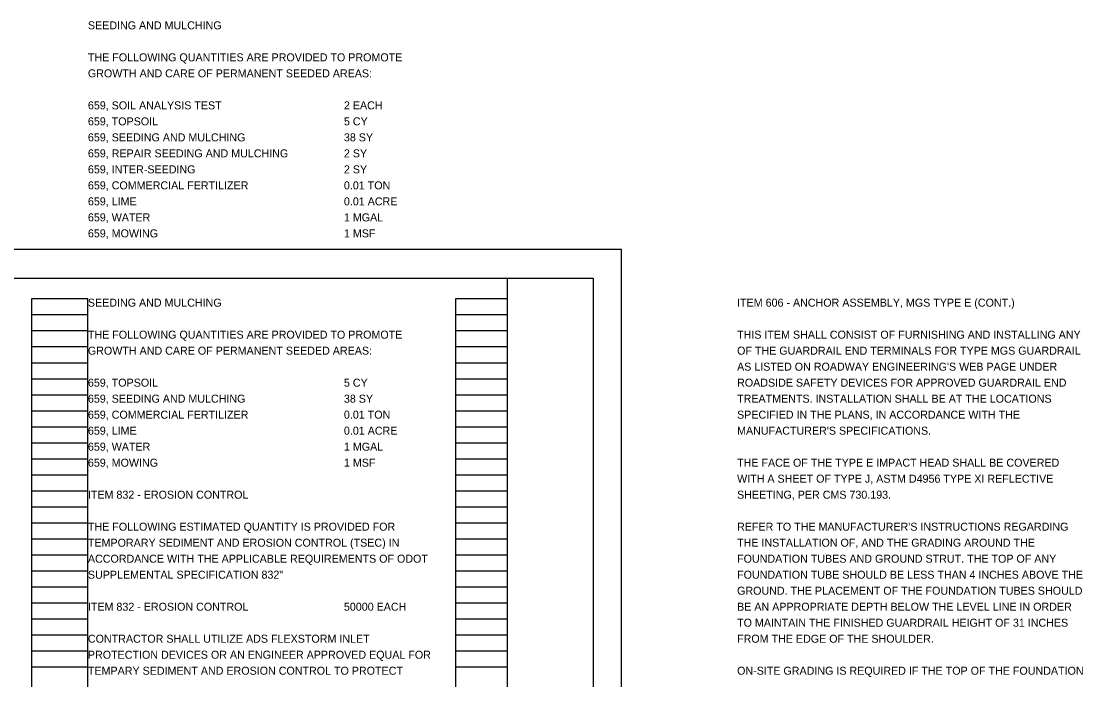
# Model space of a CAD drawing. Extents: x 0 to 42.1, y 0 to 26.
# Drawn here: x 23.49 to 42.07, y 14.47 to 25.99 of the extents above; entities that cross this region are included whole.
import ezdxf

# ---------------------------------------------------------------- set-up
doc = ezdxf.new("R2010")
doc.units = 0
for name, color, linetype in [('SH_Border', 7, 'Continuous'), ('SH_Cut_Line', 7, 'Continuous'), ('SH_Data', 7, 'Continuous'), ('SH_Text', 7, 'Continuous')]:
    doc.layers.add(name, color=color, linetype=linetype)

msp = doc.modelspace()

# ---------------------------------------------------------------- linework, layer by layer
at = {"layer": 'SH_Border'}
msp.add_line((32, 0.5), (32, 21.5), dxfattribs=at)
msp.add_lwpolyline([(1.5, 21.5), (33.5, 21.5), (33.5, 0.5), (1.5, 0.5)], close=True, dxfattribs=at)
at = {"layer": 'SH_Cut_Line'}
msp.add_lwpolyline([(0, 0), (34, 0), (34, 22), (0, 22)], close=True, dxfattribs=at)
at = {"layer": 'SH_Data'}
for p, q in [((23.68, 0.98), (23.68, 21.14)), ((23.68, 21.14), (24.66, 21.14)), ((24.66, 0.98), (24.66, 21.14)), ((31.1, 0.98), (31.1, 21.14)), ((31.1, 21.14), (32, 21.14)), ((32, 0.98), (32, 21.14)), ((23.68, 20.86), (24.66, 20.86)), ((31.1, 20.86), (32, 20.86)), ((23.68, 20.58), (24.66, 20.58)), ((31.1, 20.58), (32, 20.58)), ((23.68, 20.3), (24.66, 20.3)), ((31.1, 20.3), (32, 20.3)), ((23.68, 20.02), (24.66, 20.02)), ((31.1, 20.02), (32, 20.02)), ((23.68, 19.74), (24.66, 19.74)), ((31.1, 19.74), (32, 19.74)), ((23.68, 19.46), (24.66, 19.46)), ((31.1, 19.46), (32, 19.46)), ((23.68, 19.18), (24.66, 19.18)), ((31.1, 19.18), (32, 19.18)), ((23.68, 18.9), (24.66, 18.9)), ((31.1, 18.9), (32, 18.9)), ((23.68, 18.62), (24.66, 18.62)), ((31.1, 18.62), (32, 18.62)), ((23.68, 18.34), (24.66, 18.34)), ((31.1, 18.34), (32, 18.34)), ((23.68, 18.06), (24.66, 18.06)), ((31.1, 18.06), (32, 18.06)), ((23.68, 17.78), (24.66, 17.78)), ((31.1, 17.78), (32, 17.78)), ((23.68, 17.5), (24.66, 17.5)), ((31.1, 17.5), (32, 17.5)), ((23.68, 17.22), (24.66, 17.22)), ((31.1, 17.22), (32, 17.22)), ((23.68, 16.94), (24.66, 16.94)), ((31.1, 16.94), (32, 16.94)), ((23.68, 16.66), (24.66, 16.66)), ((31.1, 16.66), (32, 16.66)), ((23.68, 16.38), (24.66, 16.38)), ((31.1, 16.38), (32, 16.38)), ((23.68, 16.1), (24.66, 16.1)), ((31.1, 16.1), (32, 16.1)), ((23.68, 15.82), (24.66, 15.82)), ((31.1, 15.82), (32, 15.82)), ((23.68, 15.54), (24.66, 15.54)), ((31.1, 15.54), (32, 15.54)), ((23.68, 15.26), (24.66, 15.26)), ((31.1, 15.26), (32, 15.26)), ((23.68, 14.98), (24.66, 14.98)), ((31.1, 14.98), (32, 14.98)), ((23.68, 14.7), (24.66, 14.7)), ((31.1, 14.7), (32, 14.7))]:
    msp.add_line(p, q, dxfattribs=at)

# ---------------------------------------------------------------- texts
at = {"layer": 'SH_Text'}
for s, p in [('SEEDING AND MULCHING', (24.66, 25.852)), ('THE FOLLOWING QUANTITIES ARE PROVIDED TO PROMOTE ', (24.66, 25.292)), ('GROWTH AND CARE OF PERMANENT SEEDED AREAS:', (24.66, 25.012)), ('659, SOIL ANALYSIS TEST            ', (24.66, 24.452)), ('2 EACH', (29.14, 24.452)), ('659, TOPSOIL                       ', (24.66, 24.172)), ('5 CY', (29.14, 24.172)), ('659, SEEDING AND MULCHING          ', (24.66, 23.892)), ('38 SY', (29.14, 23.892)), ('659, REPAIR SEEDING AND MULCHING   ', (24.66, 23.612)), ('2 SY', (29.14, 23.612)), ('659, INTER-SEEDING                 ', (24.66, 23.332)), ('2 SY', (29.14, 23.332)), ('659, COMMERCIAL FERTILIZER         ', (24.66, 23.052)), ('0.01 TON', (29.14, 23.052)), ('659, LIME                          ', (24.66, 22.772)), ('0.01 ACRE', (29.14, 22.772)), ('659, WATER                         ', (24.66, 22.492)), ('1 MGAL', (29.14, 22.492)), ('659, MOWING                        ', (24.66, 22.212)), ('1 MSF', (29.14, 22.212)), ('SEEDING AND MULCHING', (24.66, 21)), ('ITEM 606 - ANCHOR ASSEMBLY, MGS TYPE E (CONT.)', (36.02, 21)), ('THE FOLLOWING QUANTITIES ARE PROVIDED TO PROMOTE ', (24.66, 20.44)), ('THIS ITEM SHALL CONSIST OF FURNISHING AND INSTALLING ANY ', (36.02, 20.44)), ('GROWTH AND CARE OF PERMANENT SEEDED AREAS:', (24.66, 20.16)), ('OF THE GUARDRAIL END TERMINALS FOR TYPE MGS GUARDRAIL ', (36.02, 20.16)), ("AS LISTED ON ROADWAY ENGINEERING'S WEB PAGE UNDER ", (36.02, 19.88)), ('659, TOPSOIL                       ', (24.66, 19.6)), ('5 CY', (29.14, 19.6)), ('ROADSIDE SAFETY DEVICES FOR APPROVED GUARDRAIL END ', (36.02, 19.6)), ('659, SEEDING AND MULCHING          ', (24.66, 19.32)), ('38 SY', (29.14, 19.32)), ('TREATMENTS. INSTALLATION SHALL BE AT THE LOCATIONS ', (36.02, 19.32)), ('659, COMMERCIAL FERTILIZER         ', (24.66, 19.04)), ('0.01 TON', (29.14, 19.04)), ('SPECIFIED IN THE PLANS, IN ACCORDANCE WITH THE ', (36.02, 19.04)), ('659, LIME                          ', (24.66, 18.76)), ('0.01 ACRE', (29.14, 18.76)), ("MANUFACTURER'S SPECIFICATIONS.", (36.02, 18.76)), ('659, WATER                         ', (24.66, 18.48)), ('1 MGAL', (29.14, 18.48)), ('659, MOWING                        ', (24.66, 18.2)), ('1 MSF', (29.14, 18.2)), ('THE FACE OF THE TYPE E IMPACT HEAD SHALL BE COVERED ', (36.02, 18.2)), ('WITH A SHEET OF TYPE J, ASTM D4956 TYPE XI REFLECTIVE ', (36.02, 17.92)), ('ITEM 832 - EROSION CONTROL', (24.66, 17.64)), ('SHEETING, PER CMS 730.193.', (36.02, 17.64)), ('THE FOLLOWING ESTIMATED QUANTITY IS PROVIDED FOR ', (24.66, 17.08)), ("REFER TO THE MANUFACTURER'S INSTRUCTIONS REGARDING ", (36.02, 17.08)), ('TEMPORARY SEDIMENT AND EROSION CONTROL (TSEC) IN ', (24.66, 16.8)), ('THE INSTALLATION OF, AND THE GRADING AROUND THE ', (36.02, 16.8)), ('ACCORDANCE WITH THE APPLICABLE REQUIREMENTS OF ODOT ', (24.66, 16.52)), ('FOUNDATION TUBES AND GROUND STRUT. THE TOP OF ANY ', (36.02, 16.52)), ('SUPPLEMENTAL SPECIFICATION 832"', (24.66, 16.24)), ('FOUNDATION TUBE SHOULD BE LESS THAN 4 INCHES ABOVE THE ', (36.02, 16.24)), ('GROUND. THE PLACEMENT OF THE FOUNDATION TUBES SHOULD ', (36.02, 15.96)), ('ITEM 832 - EROSION CONTROL', (24.66, 15.68)), ('50000 EACH', (29.14, 15.68)), ('BE AN APPROPRIATE DEPTH BELOW THE LEVEL LINE IN ORDER ', (36.02, 15.68)), ('TO MAINTAIN THE FINISHED GUARDRAIL HEIGHT OF 31 INCHES ', (36.02, 15.4)), ('CONTRACTOR SHALL UTILIZE ADS FLEXSTORM INLET ', (24.66, 15.12)), ('FROM THE EDGE OF THE SHOULDER.', (36.02, 15.12)), ('PROTECTION DEVICES OR AN ENGINEER APPROVED EQUAL FOR ', (24.66, 14.84)), ('TEMPARY SEDIMENT AND EROSION CONTROL TO PROTECT ', (24.66, 14.56)), ('ON-SITE GRADING IS REQUIRED IF THE TOP OF THE FOUNDATION ', (36.02, 14.56))]:
    msp.add_text(s, height=0.14, dxfattribs=at).set_placement(p)

doc.saveas('drawing.dxf')
